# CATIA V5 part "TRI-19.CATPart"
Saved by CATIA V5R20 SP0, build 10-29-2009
Part number: _TRI-19
Definition: NONE
Nomenclature: _TRI-19
Source: Unknown
Description: PART-_TRI-19-DESC
Bounding box of the stored display mesh (mm): x 0 to 22.5, y -9.5 to 9.5, z -9.5 to 9.5
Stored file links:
  C:\Users\Utente\Desktop\IO LAVORO\3D X SITO CF\X SITO\PLASTICA\TRI\TRI-19.CATPart
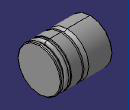
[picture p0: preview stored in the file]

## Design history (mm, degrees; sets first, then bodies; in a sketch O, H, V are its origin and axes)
Body1 "_TRI-19" (main body)
  Solid1: solid without history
